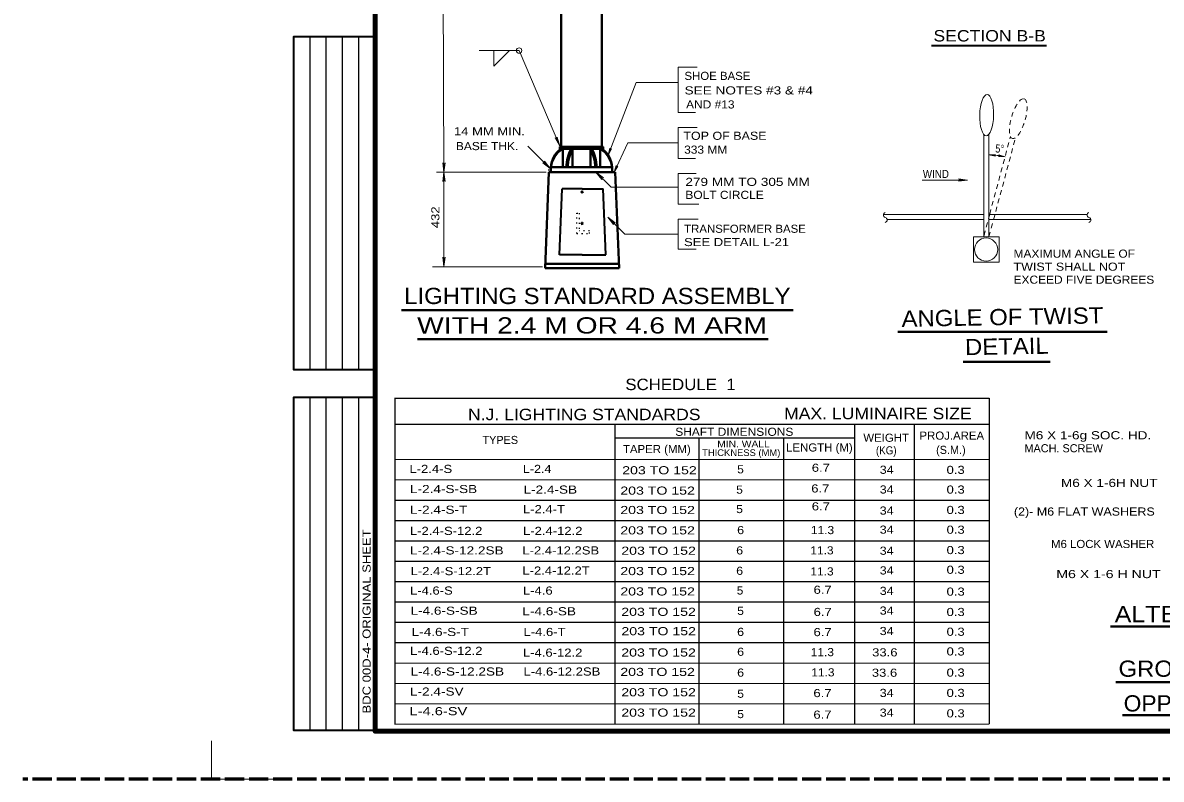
# Model space of a CAD drawing. Extents: x 312583 to 312854, y 144418 to 144597.
# Drawn here: x 312583.5 to 312690.1, y 144418.6 to 144489.4 of the extents above; entities that cross this region are included whole.
import ezdxf
from ezdxf.enums import TextEntityAlignment as Align

# ---------------------------------------------------------------- set-up
doc = ezdxf.new("R2010")
doc.units = 0
doc.header["$LTSCALE"] = 0.3
for name, pattern in [('DOTTED', [1.5, 0.3, -1.2]), ('LONG_DASHED', [7.5, 6, -1.5]), ('SHORT_DASHED', [2.7, 1.5, -1.2])]:
    doc.linetypes.add(name, pattern=pattern)
doc.layers.add('1', color=7, linetype='Continuous', lineweight=35)

msp = doc.modelspace()

# ---------------------------------------------------------------- linework, layer by layer
at = {"layer": '1', "lineweight": 158}
for p, q in [((312616.5, 144423.1446), (312616.5, 144585.0846)), ((312616.5, 144423.0846), (312849, 144423.0846))]:
    msp.add_line(p, q, dxfattribs=at)
at = {"layer": '1', "lineweight": 40}
for p, q in [((312633.9075, 144498.2908), (312633.9075, 144477.8024)), ((312637.72, 144498.2908), (312637.72, 144477.8024)), ((312633.7855, 144477.8024), (312635.8138, 144477.8024)), ((312633.7855, 144477.8024), (312633.7855, 144477.6194)), ((312633.7855, 144477.6194), (312635.8138, 144477.6194)), ((312634.06, 144475.8962), (312634.06, 144477.6194)), ((312634.975, 144477.6194), (312634.975, 144475.9572)), ((312637.8344, 144477.8024), (312635.8138, 144477.8024)), ((312637.8344, 144477.6194), (312635.8138, 144477.6194)), ((312636.6449, 144477.6194), (312636.6449, 144475.9572)), ((312637.5675, 144475.8962), (312637.5675, 144477.6194)), ((312637.8344, 144477.8024), (312637.8344, 144477.6194)), ((312632.3978, 144466.4488), (312632.7638, 144475.4158)), ((312635.8595, 144475.4158), (312632.7638, 144475.4158)), ((312632.9544, 144475.8962), (312635.8138, 144475.8962)), ((312632.9544, 144475.8962), (312632.9544, 144475.4158)), ((312632.9544, 144475.4158), (312635.8138, 144475.4158)), ((312638.6731, 144475.8962), (312635.8138, 144475.8962)), ((312638.6731, 144475.4158), (312635.8138, 144475.4158)), ((312635.8595, 144475.4158), (312638.9629, 144475.4158)), ((312638.6731, 144475.8962), (312638.6731, 144475.4158)), ((312639.3212, 144466.4488), (312638.9629, 144475.4158)), ((312632.3978, 144466.4488), (312639.3212, 144466.4488)), ((312632.413, 144466.8377), (312639.306, 144466.8377)), ((312618.9635, 144462.5179), (312655.6233, 144462.5179)), ((312684.9972, 144460.4836), (312665.4004, 144460.4836)), ((312620.4494, 144459.7922), (312653.2826, 144459.7922)), ((312679.6768, 144457.6636), (312671.5189, 144457.6636)), ((312685.2992, 144432.8731), (312712.8571, 144432.8731)), ((312685.8118, 144427.6822), (312711.394, 144427.6822)), ((312686.4325, 144424.594), (312710.3473, 144424.594))]:
    msp.add_line(p, q, dxfattribs=at)
at = {"layer": '1', "lineweight": 25}
for p, q in [((312610.4087, 144456.901), (312610.4087, 144488.1192)), ((312611.9315, 144456.901), (312611.9315, 144488.1192)), ((312613.4543, 144456.901), (312613.4543, 144488.1192)), ((312614.9772, 144456.901), (312614.9772, 144488.1192)), ((312633.7855, 144477.8024), (312633.9075, 144477.9168)), ((312637.8344, 144477.8024), (312637.72, 144477.9168)), ((312610.4087, 144423.1446), (312610.4087, 144454.3629)), ((312611.9315, 144423.1446), (312611.9315, 144454.3629)), ((312613.4543, 144423.1446), (312613.4543, 144454.3629)), ((312614.9772, 144423.1446), (312614.9772, 144454.3629)), ((312618.3022, 144454.2488), (312673.9704, 144454.2583)), ((312618.3534, 144454.2553), (312618.3534, 144423.7488)), ((312673.9704, 144454.2583), (312673.9704, 144423.7583)), ((312618.302, 144451.8342), (312673.9704, 144451.8437)), ((312638.9413, 144451.8377), (312638.9413, 144423.7553)), ((312661.35, 144451.8415), (312661.35, 144423.7553)), ((312666.9352, 144451.8425), (312666.9352, 144423.7553)), ((312638.9413, 144450.5534), (312661.35, 144450.5534)), ((312646.8025, 144450.5534), (312646.8025, 144423.7553)), ((312654.698, 144450.5534), (312654.698, 144423.7553)), ((312618.3022, 144448.5301), (312673.9704, 144448.5396)), ((312618.3022, 144446.6238), (312673.9704, 144446.6333)), ((312618.3022, 144444.7175), (312673.9704, 144444.727)), ((312618.3022, 144442.8113), (312673.9704, 144442.8208)), ((312618.3022, 144440.9051), (312673.9704, 144440.9146)), ((312618.3022, 144438.9988), (312673.9704, 144439.0083)), ((312618.3022, 144437.0925), (312673.9704, 144437.102)), ((312618.3022, 144435.1863), (312673.9704, 144435.1958)), ((312618.3022, 144433.2801), (312673.9704, 144433.2896)), ((312618.3022, 144431.3738), (312673.9704, 144431.3833)), ((312618.3022, 144429.4675), (312673.9704, 144429.477)), ((312618.3022, 144427.5613), (312673.9704, 144427.5708)), ((312618.3022, 144425.6551), (312673.9704, 144425.6646)), ((312618.3534, 144423.7488), (312673.9704, 144423.7583))]:
    msp.add_line(p, q, dxfattribs=at)
at = {"layer": '1', "lineweight": 13}
for p, q in [((312629.973, 144486.8076), (312626.2291, 144486.8076)), ((312633.7779, 144477.871), (312629.973, 144486.8076)), ((312644.857, 144485.2597), (312644.857, 144481.0202)), ((312644.857, 144485.2597), (312646.6336, 144485.2597)), ((312638.3071, 144477.0247), (312640.9225, 144483.8186)), ((312640.9225, 144483.8186), (312644.8646, 144483.8186)), ((312643.3854, 144483.8186), (312644.8112, 144483.8186)), ((312644.857, 144481.0202), (312646.4735, 144481.0202)), ((312644.857, 144479.6172), (312644.857, 144476.712)), ((312644.857, 144479.6172), (312646.6336, 144479.6172)), ((312633.3432, 144478.6259), (312633.5491, 144478.4124)), ((312633.7779, 144477.871), (312633.3432, 144478.6259)), ((312633.5339, 144478.7098), (312633.5491, 144478.4124)), ((312633.7779, 144477.871), (312633.5339, 144478.7098)), ((312640.1448, 144478.176), (312638.8638, 144475.4158)), ((312640.1448, 144478.176), (312644.8646, 144478.176)), ((312673.4554, 144471.4518), (312673.4554, 144478.9548)), ((312673.9357, 144469.3778), (312673.9357, 144478.9243)), ((312630.7736, 144477.8558), (312632.8705, 144475.7589)), ((312638.3071, 144477.0247), (312638.4749, 144477.6576)), ((312638.3071, 144477.0247), (312638.6198, 144477.5966)), ((312638.4749, 144477.6576), (312638.4672, 144477.4364)), ((312638.6198, 144477.5966), (312638.4672, 144477.4364)), ((312673.9357, 144477.0409), (312674.5534, 144477.0867)), ((312674.5534, 144477.0867), (312674.3475, 144477.0257)), ((312622.836, 144476.2927), (312622.9428, 144476.0182)), ((312622.9428, 144475.431), (312622.836, 144476.2927)), ((312623.0495, 144476.2927), (312622.9428, 144476.0182)), ((312622.9428, 144475.431), (312623.0495, 144476.2927)), ((312632.1842, 144476.2927), (312632.4511, 144476.1707)), ((312632.8705, 144475.7589), (312632.1842, 144476.2927)), ((312632.3368, 144476.4452), (312632.4511, 144476.1707)), ((312632.8705, 144475.7589), (312632.3368, 144476.4452)), ((312638.8638, 144475.4158), (312639.0544, 144476.041)), ((312639.0544, 144476.041), (312639.0468, 144475.8199)), ((312644.857, 144476.712), (312646.4735, 144476.712)), ((312673.9357, 144477.0409), (312674.5457, 144476.9341)), ((312674.5457, 144476.9341), (312674.3475, 144477.0257)), ((312674.8278, 144476.8884), (312675.0337, 144476.9418)), ((312675.4455, 144476.8655), (312674.8278, 144476.8884)), ((312674.8507, 144477.0409), (312675.0337, 144476.9418)), ((312675.4455, 144476.8655), (312674.8507, 144477.0409)), ((312632.5198, 144475.4158), (312622.2565, 144475.4158)), ((312622.9428, 144475.4082), (312622.836, 144474.5466)), ((312622.9428, 144466.5937), (312622.9428, 144475.4082)), ((312622.9428, 144475.4082), (312623.0495, 144474.5466)), ((312632.7638, 144475.5378), (312632.7638, 144475.7132)), ((312637.1634, 144475.4158), (312637.7048, 144474.7448)), ((312637.1634, 144475.4158), (312637.8572, 144474.8973)), ((312638.574, 144474.0204), (312637.1634, 144475.4158)), ((312637.7048, 144474.7448), (312637.5828, 144475.0117)), ((312637.8572, 144474.8973), (312637.5828, 144475.0117)), ((312638.8638, 144475.4158), (312639.1992, 144475.9724)), ((312639.1992, 144475.9724), (312639.0468, 144475.8199)), ((312644.857, 144475.309), (312644.857, 144472.4116)), ((312644.857, 144475.309), (312646.5269, 144475.309)), ((312622.836, 144474.5466), (312622.9428, 144474.821)), ((312623.0495, 144474.5466), (312622.9428, 144474.821)), ((312644.857, 144474.0204), (312638.574, 144474.0204)), ((312671.9456, 144474.6771), (312667.6832, 144474.6771)), ((312671.084, 144474.7839), (312671.3585, 144474.6771)), ((312671.9456, 144474.6771), (312671.084, 144474.7839)), ((312671.084, 144474.5704), (312671.3585, 144474.6771)), ((312671.9456, 144474.6771), (312671.084, 144474.5704)), ((312644.857, 144472.4116), (312646.8014, 144472.4116)), ((312639.8626, 144469.6056), (312638.2614, 144471.1992)), ((312638.2614, 144471.1992), (312638.8028, 144470.5282)), ((312638.2614, 144471.1992), (312638.9552, 144470.6807)), ((312638.8028, 144470.5282), (312638.6808, 144470.795)), ((312638.9552, 144470.6807), (312638.6808, 144470.795)), ((312644.857, 144471.0086), (312644.857, 144468.2026)), ((312673.4477, 144471.4518), (312664.0537, 144471.4518)), ((312673.4554, 144470.9943), (312664.4197, 144470.9943)), ((312673.4554, 144469.3625), (312673.4554, 144471.4441)), ((312683.467, 144470.9943), (312673.9281, 144470.9943)), ((312683.1238, 144471.4518), (312673.9434, 144471.4518)), ((312639.8626, 144469.6056), (312644.8265, 144469.6056)), ((312674.8888, 144469.3701), (312674.8888, 144466.9911)), ((312644.857, 144468.2026), (312646.5269, 144468.2026)), ((312632.1461, 144466.5556), (312621.8829, 144466.5556)), ((312622.836, 144467.4553), (312622.9428, 144467.1808)), ((312622.9428, 144466.5937), (312622.836, 144467.4553)), ((312623.0495, 144467.4553), (312622.9428, 144467.1808)), ((312622.9428, 144466.5937), (312623.0495, 144467.4553)), ((312674.8888, 144466.9911), (312672.5022, 144466.9911)), ((312601.2, 144422.1846), (312601.2, 144418.5846)), ((312601.2, 144418.5846), (312608.1, 144418.5846))]:
    msp.add_line(p, q, dxfattribs=at)
at = {"layer": '1'}
for p, q in [((312668.5605, 144487.2829), (312679.3121, 144487.2829)), ((312633.7626, 144467.6688), (312634.0142, 144473.8679)), ((312635.8595, 144473.8679), (312634.0142, 144473.8679)), ((312635.8595, 144473.8679), (312637.8344, 144473.8679)), ((312638.086, 144467.6688), (312637.8344, 144473.8679)), ((312635.8595, 144467.6688), (312633.7626, 144467.6688)), ((312635.8595, 144467.6688), (312638.086, 144467.6688))]:
    msp.add_line(p, q, dxfattribs=at)
at = {"layer": '1', "linetype": 'SHORT_DASHED', "lineweight": 13}
for p, q in [((312673.9434, 144469.3854), (312676.4215, 144478.6345)), ((312674.012, 144471.5051), (312675.9564, 144478.7641)), ((312673.4782, 144469.4845), (312674.012, 144471.4975))]:
    msp.add_line(p, q, dxfattribs=at)
at = {"layer": '1', "linetype": 'DOTTED', "lineweight": 25}
msp.add_line((312635.6002, 144471.5957), (312635.6002, 144469.9258), dxfattribs=at)
at = {"layer": '1', "linetype": 'LONG_DASHED', "lineweight": 60}
msp.add_line((312851.75, 144418.5846), (312583.526, 144418.5846), dxfattribs=at)
at = {"layer": '1', "lineweight": 158}
msp.add_lwpolyline([(312849, 144423.0846), (312849, 144585.0846), (312616.5, 144585.0846), (312616.5, 144423.0846)], close=True, dxfattribs=at)
msp.add_lwpolyline([(312616.5, 144585.0846), (312616.5, 144423.0846), (312849, 144423.0846)], dxfattribs=at)
at = {"layer": '1', "lineweight": 13}
for points in [[(312622.9428, 144475.431), (312622.7674, 144518.4208), (312622.7674, 144551.315)], [(312627.6016, 144486.8152), (312627.6016, 144485.3359), (312629.0732, 144486.8076)], [(312644.857, 144471.0086), (312646.6336, 144471.0086), (312646.7404, 144471.0086)], [(312674.8888, 144469.3701), (312672.5022, 144469.3701), (312672.5022, 144466.9911)]]:
    msp.add_lwpolyline(points, dxfattribs=at)
at = {"layer": '1'}
for points in [[(312616.5, 144456.901), (312608.8858, 144456.901), (312608.8858, 144488.1192), (312616.5, 144488.1192)], [(312616.5, 144423.1446), (312608.8858, 144423.1446), (312608.8858, 144454.3629), (312616.5, 144454.3629)]]:
    msp.add_lwpolyline(points, dxfattribs=at)
at = {"layer": '1', "linetype": 'DOTTED', "lineweight": 25}
for points in [[(312635.3639, 144469.6894), (312635.3639, 144471.5957), (312635.6002, 144471.5957)], [(312635.3639, 144469.6894), (312636.5534, 144469.6894), (312636.5534, 144469.9258), (312635.6002, 144469.9258)]]:
    msp.add_lwpolyline(points, dxfattribs=at)
at = {"layer": '1', "lineweight": 13}
for centre, radius in [((312629.9725, 144486.8066), 0.2541), ((312673.6765, 144468.1806), 1.0828)]:
    msp.add_circle(centre, radius, dxfattribs=at)
at = {"layer": '1', "lineweight": 40}
for centre in [(312635.8628, 144473.5686), (312635.8624, 144470.6278)]:
    msp.add_circle(centre, 0.0596, dxfattribs=at)
for centre, radius, start, end in [((312635.1362, 144475.8132), 2.1867, 124.21849, 177.88724), ((312635.3495, 144475.576), 2.4194, 122.28719, 172.4519), ((312638.7942, 144475.6386), 4.4211, 153.35491, 176.59885), ((312638.7942, 144475.6386), 4.3019, 152.55593, 176.59975), ((312632.8266, 144475.6386), 4.3019, 3.40025, 27.44407), ((312632.8266, 144475.6386), 4.4211, 3.40115, 26.64509), ((312636.2713, 144475.576), 2.4194, 7.5481, 57.71281), ((312636.4846, 144475.8132), 2.1867, 2.11276, 55.78151), ((312635.036, 144475.9534), 0.0596, 180, 270), ((312636.5848, 144475.9534), 0.0596, 270, 0)]:
    msp.add_arc(centre, radius, start, end, dxfattribs=at)
at = {"layer": '1', "lineweight": 13}
for centre, radius, start, end in [((312673.8061, 144469.3168), 7.7271, 77.72979, 89.03856), ((312664.2983, 144471.4149), 0.2381, 105, 255), ((312664.1751, 144470.9549), 0.2381, 285, 75), ((312683.3608, 144471.4149), 0.2381, 105, 255), ((312683.2376, 144470.9549), 0.2381, 285, 75)]:
    msp.add_arc(centre, radius, start, end, dxfattribs=at)
msp.add_ellipse((312673.726, 144480.7581), major_axis=(0.0496, 1.9329), ratio=0.33587, dxfattribs=at)
at = {"layer": '1', "linetype": 'SHORT_DASHED', "lineweight": 13}
msp.add_ellipse((312676.6862, 144480.4322), major_axis=(0.5482, 1.8542), ratio=0.33587, dxfattribs=at)

# ---------------------------------------------------------------- texts
at = {"layer": '1'}
for s, height, width, p in [('SECTION B-B', 1.07, 1.15, (312674.0038, 144487.6577)), ('LIGHTING STANDARD ASSEMBLY', 1.52, 1.1, (312637.2967, 144463.0741)), ('WITH 2.4 M OR 4.6 M ARM', 1.52, 1.3, (312636.7997, 144460.3167)), ('SCHEDULE  1', 1.07, 1.1, (312645.0744, 144455.0172)), ('N.J. LIGHTING STANDARDS', 1.07, 1.15, (312636.0679, 144452.2034)), ('MAX. LUMINAIRE SIZE', 1.07, 1.15, (312663.5443, 144452.2921)), ('THICKNESS (MM)', 0.6253, 1.05, (312650.7597, 144448.8458)), ('MIN. WALL', 0.6253, 1.15, (312650.968, 144449.6614)), ('ALTERNATE DETAIL "D"', 1.52, 1.15, (312699.0049, 144433.2825)), ('GROUND STUD DETAIL', 1.52, 1.1, (312698.6081, 144428.1769)), ('OPPOSITE HANDHOLE', 1.52, 1.05, (312698.2257, 144424.93))]:
    msp.add_text(s, height=height, dxfattribs=dict(at, width=width)).set_placement(p, align=Align.CENTER)
for s, width, p in [('SHOE BASE', 1.05, (312645.4472, 144484.0581)), ('SEE NOTES #3 & #4', 1.25, (312645.4598, 144482.6981)), ('AND #13', 1.1, (312645.5958, 144481.3838)), ('14 MM MIN.', 1.2, (312623.873, 144478.8724)), ('TOP OF BASE', 1.15, (312645.3391, 144478.451)), ('BASE THK.', 1.1, (312624.0557, 144477.4847)), ('333 MM', 1.1, (312645.4144, 144477.1521)), ('WIND', 0.9, (312667.7519, 144474.88)), ('279 MM TO 305 MM', 1.25, (312645.5322, 144474.1347)), ('BOLT CIRCLE', 1.1, (312645.5322, 144472.9172)), ('TRANSFORMER BASE', 1.05, (312645.4166, 144469.7461)), ('SEE DETAIL L-21', 1.2, (312645.4081, 144468.5015)), ('MAXIMUM ANGLE OF', 1.1, (312676.2385, 144467.413)), ('TWIST SHALL NOT', 1.15, (312676.2385, 144466.1955)), ('EXCEED FIVE DEGREES', 1.1, (312676.2385, 144464.978)), ('SHAFT DIMENSIONS', 1.1, (312644.5829, 144450.7372)), ('WEIGHT ', 1.05, (312662.1849, 144450.1795)), ('PROJ.AREA', 1.05, (312667.4377, 144450.3757)), ('M6 X 1-6g SOC. HD.', 1.25, (312677.2625, 144450.4112)), ('TAPER (MM)', 1.05, (312639.691, 144449.1185)), ('LENGTH (M)', 1.05, (312654.9622, 144449.2696)), ('(KG)', 0.9, (312663.3633, 144448.9989)), ('L-2.4-S', 1.2, (312619.7106, 144447.2608)), ('L-2.4', 1.15, (312630.3324, 144447.2608)), ('203 TO 152 ', 1.3, (312639.62, 144447.134)), ('5 ', 1.1, (312650.3788, 144447.2228)), ('6.7 ', 1.2, (312657.3593, 144447.3684)), ('34 ', 1.15, (312663.7175, 144447.181)), ('0.3 ', 1.2, (312669.9748, 144447.1729)), ('6.7 ', 1.2, (312657.3102, 144445.4316)), ('M6 X 1-6H NUT', 1.25, (312680.6765, 144445.9487)), ('L-2.4-S-SB', 1.25, (312619.764, 144445.3775)), ('L-2.4-SB', 1.25, (312630.3857, 144445.3241)), ('203 TO 152 ', 1.3, (312639.4446, 144445.2278)), ('5 ', 1.1, (312650.2873, 144445.3166)), ('34 ', 1.15, (312663.7175, 144445.3357)), ('0.3 ', 1.2, (312669.9748, 144445.3277)), ('L-2.4-S-T', 1.25, (312619.764, 144443.4407)), ('L-2.4-T', 1.2, (312630.3324, 144443.4941)), ('203 TO 152 ', 1.3, (312639.4446, 144443.413)), ('5 ', 1.1, (312650.2873, 144443.5018)), ('6.7 ', 1.2, (312657.3593, 144443.7541)), ('34 ', 1.15, (312663.7175, 144443.3608)), ('0.3 ', 1.2, (312669.9748, 144443.4214)), ('(2)- M6 FLAT WASHERS', 1.15, (312676.2742, 144443.269)), ('L-2.4-S-12.2', 1.2, (312619.7563, 144441.4582)), ('L-2.4-12.2', 1.2, (312630.34, 144441.4582)), ('203 TO 152 ', 1.3, (312639.4446, 144441.5068)), ('6 ', 1.15, (312650.3764, 144441.5346)), ('11.3 ', 1.1, (312657.2733, 144441.5331)), ('34 ', 1.15, (312663.7175, 144441.5766)), ('0.3 ', 1.2, (312669.9748, 144441.5686)), ('M6 LOCK WASHER', 1.05, (312679.7476, 144440.2306)), ('L-2.4-S-12.2SB', 1.25, (312619.764, 144439.6282)), ('L-2.4-12.2SB', 1.2, (312630.279, 144439.6282)), ('203 TO 152 ', 1.3, (312639.5361, 144439.6005)), ('6 ', 1.15, (312650.2848, 144439.6283)), ('11.3 ', 1.1, (312657.2242, 144439.6359)), ('34 ', 1.15, (312663.7175, 144439.6017)), ('0.3 ', 1.2, (312669.9748, 144439.6623)), ('L-2.4-S-12.2T', 1.2, (312619.8173, 144437.6915)), ('L-2.4-12.2T', 1.2, (312630.279, 144437.7448)), ('203 TO 152 ', 1.3, (312639.4446, 144437.6943)), ('6 ', 1.15, (312650.2848, 144437.7221)), ('11.3 ', 1.1, (312657.229, 144437.6624)), ('34 ', 1.15, (312663.7175, 144437.7564)), ('0.3 ', 1.2, (312669.9748, 144437.817)), ('M6 X 1-6 H NUT', 1.3, (312680.2385, 144437.4156)), ('L-4.6-S', 1.2, (312619.764, 144435.8691)), ('L-4.6', 1.2, (312630.3324, 144435.8691)), ('5 ', 1.1, (312650.3373, 144435.8768)), ('6.7 ', 1.2, (312657.5271, 144435.9461)), ('34 ', 1.15, (312663.7175, 144435.8426)), ('203 TO 152 ', 1.3, (312639.4446, 144435.788)), ('0.3 ', 1.2, (312669.9748, 144435.7736)), ('L-4.6-S-SB', 1.25, (312619.8097, 144433.9857)), ('L-4.6-SB', 1.25, (312630.279, 144433.9324)), ('203 TO 152 ', 1.3, (312639.5361, 144433.8818)), ('5 ', 1.1, (312650.3816, 144433.9706)), ('6.7 ', 1.2, (312657.5318, 144433.8714)), ('34 ', 1.15, (312663.7175, 144433.9973)), ('0.3 ', 1.2, (312669.9748, 144433.8673)), ('L-4.6-S-T', 1.25, (312619.9164, 144431.9956)), ('L-4.6-T', 1.2, (312630.3857, 144431.9956)), ('203 TO 152 ', 1.3, (312639.5437, 144432.067)), ('6 ', 1.15, (312650.3764, 144432.0033)), ('6.7 ', 1.2, (312657.5223, 144431.9817)), ('34 ', 1.15, (312663.7175, 144432.0834)), ('0.3 ', 1.2, (312669.9748, 144432.0144)), ('L-4.6-S-12.2', 1.2, (312619.764, 144430.2266)), ('L-4.6-12.2', 1.2, (312630.3324, 144430.0588)), ('203 TO 152 ', 1.3, (312639.5361, 144430.0693)), ('6 ', 1.15, (312650.3764, 144430.1397)), ('11.3 ', 1.1, (312657.2638, 144430.1061)), ('33.6 ', 1.2, (312663.0087, 144430.0844)), ('0.3 ', 1.2, (312669.9748, 144430.1692)), ('L-4.6-S-12.2SB', 1.25, (312619.8097, 144428.2898)), ('L-4.6-12.2SB', 1.2, (312630.3857, 144428.2898)), ('203 TO 152 ', 1.3, (312639.4446, 144428.2545)), ('6 ', 1.15, (312650.3764, 144428.1908)), ('11.3 ', 1.1, (312657.3129, 144428.2136)), ('33.6 ', 1.2, (312662.981, 144428.178)), ('0.3 ', 1.2, (312669.9748, 144428.1943)), ('L-2.4-SV', 1.25, (312619.764, 144426.4141)), ('203 TO 152 ', 1.3, (312639.5361, 144426.3483)), ('6.7 ', 1.2, (312657.5127, 144426.2707)), ('34 ', 1.15, (312663.7175, 144426.2884)), ('0.3 ', 1.2, (312669.9748, 144426.288)), ('5 ', 1.1, (312650.3872, 144426.2126)), ('L-4.6-SV              ', 1.35, (312619.7125, 144424.5783)), ('203 TO 152 ', 1.3, (312639.5361, 144424.442)), ('5 ', 1.1, (312650.3873, 144424.3089)), ('6.7 ', 1.2, (312657.5127, 144424.2527)), ('34 ', 1.15, (312663.7175, 144424.4432)), ('0.3 ', 1.2, (312669.9748, 144424.3742))]:
    msp.add_text(s, height=0.76, dxfattribs=dict(at, width=width)).set_placement(p)
for s, height, rotation, width, p in [('5°', 0.76, 356, 0.85, (312674.5103, 144477.2735)), ('432 ', 0.76, 90, 1.2, (312622.5143, 144470.1822)), ('BDC 00D-4- ORIGINAL SHEET', 0.7614, 90, 1.2, (312616.0832, 144424.7374))]:
    msp.add_text(s, height=height, rotation=rotation, dxfattribs=dict(at, width=width)).set_placement(p)
at = {"layer": '1', "width": 1.1}
for s, p in [('ANGLE OF TWIST', (312675.2107, 144461.1025)), ('DETAIL', (312675.623, 144458.3539))]:
    msp.add_text(s, height=1.52, rotation=1, dxfattribs=at).set_placement(p, align=Align.CENTER)
at = {"layer": '1'}
for s, p in [('TYPES', (312626.5433, 144449.9694)), ('(S.M.)', (312668.9941, 144449.0432)), ('MACH. SCREW', (312677.2625, 144449.1937))]:
    msp.add_text(s, height=0.76, dxfattribs=at).set_placement(p)

doc.saveas('drawing.dxf')
